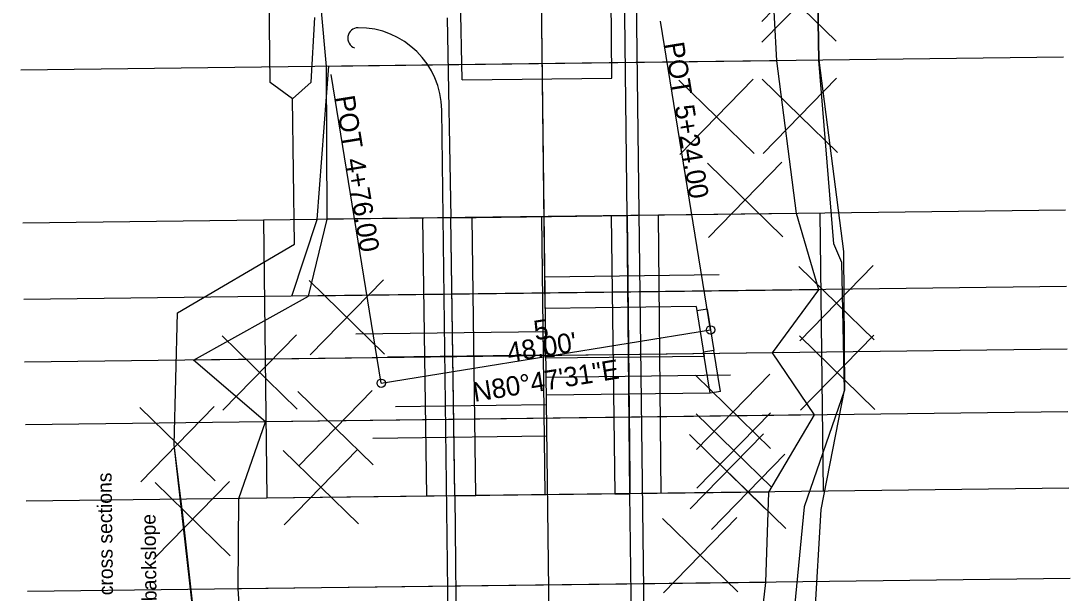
# Model space of a CAD drawing. Extents: x 2341000 to 2341204, y 624110 to 624511.
# Drawn here: x 2341050.8 to 2341201.7, y 624284.3 to 624366.6 of the extents above; entities that cross this region are included whole.
import ezdxf

# ---------------------------------------------------------------- set-up
doc = ezdxf.new("R2010")
doc.units = 0
for name, color, linetype in [('GE_P_Alignment', 7, 'Continuous'), ('GE_P_Alignment_1000_Bearings', 7, 'Continuous'), ('GE_P_Alignment_1000_Cardinal_Points', 7, 'Continuous'), ('GE_P_Alignment_1000_Distances', 7, 'Continuous'), ('GE_P_Alignment_1000_Stations', 7, 'Continuous'), ('GE_P_Alignment_100_Bearings', 7, 'Continuous'), ('GE_P_Alignment_100_Cardinal_Points', 7, 'Continuous'), ('GE_P_Alignment_100_Distances', 7, 'Continuous'), ('GE_P_Alignment_100_Stations', 7, 'Continuous'), ('GE_P_Alignment_500_Bearings', 7, 'Continuous'), ('GE_P_Alignment_500_Cardinal_Points', 7, 'Continuous'), ('GE_P_Alignment_500_Distances', 7, 'Continuous'), ('GE_P_Alignment_500_Stations', 7, 'Continuous'), ('PV_P_EOP', 7, 'Continuous'), ('PV_P_Joint', 7, 'Continuous'), ('PV_P_Shoulder', 7, 'Continuous'), ('RD_P_GR_Lt', 7, 'Continuous'), ('RD_P_GR_Rt', 7, 'Continuous'), ('RW_P_Const_Limits', 7, 'Continuous'), ('SC_Scratch1', 7, 'Continuous'), ('SC_Scratch10', 7, 'Continuous'), ('SC_Scratch2', 7, 'Continuous'), ('SC_Scratch3', 7, 'Continuous'), ('SC_Scratch5', 7, 'Continuous'), ('VG_P_Cells', 7, 'Continuous')]:
    doc.layers.add(name, color=color, linetype=linetype)

msp = doc.modelspace()

# ---------------------------------------------------------------- linework, layer by layer
at = {"layer": 'GE_P_Alignment'}
msp.add_line((2341102.63, 624314.5), (2341150.02, 624322.18), dxfattribs=at)
at = {"layer": 'GE_P_Alignment_1000_Cardinal_Points'}
for p, q in [((2341150.02, 624322.18), (2341142.81, 624366.6)), ((2341102.63, 624314.5), (2341095.43, 624358.92))]:
    msp.add_line(p, q, dxfattribs=at)
for centre in [(2341150.02, 624322.18), (2341102.63, 624314.5)]:
    msp.add_circle(centre, 0.6, dxfattribs=at)
at = {"layer": 'GE_P_Alignment_1000_Stations'}
msp.add_line((2341126.32, 624318.34), (2341126.13, 624319.53), dxfattribs=at)
at = {"layer": 'GE_P_Alignment_100_Cardinal_Points'}
for p, q in [((2341150.02, 624322.18), (2341142.81, 624366.6)), ((2341102.63, 624314.5), (2341095.43, 624358.92))]:
    msp.add_line(p, q, dxfattribs=at)
for centre in [(2341150.02, 624322.18), (2341102.63, 624314.5)]:
    msp.add_circle(centre, 0.6, dxfattribs=at)
at = {"layer": 'GE_P_Alignment_100_Stations'}
msp.add_line((2341126.32, 624318.34), (2341126, 624320.32), dxfattribs=at)
at = {"layer": 'GE_P_Alignment_500_Cardinal_Points'}
for p, q in [((2341150.02, 624322.18), (2341142.81, 624366.6)), ((2341102.63, 624314.5), (2341095.43, 624358.92))]:
    msp.add_line(p, q, dxfattribs=at)
for centre in [(2341150.02, 624322.18), (2341102.63, 624314.5)]:
    msp.add_circle(centre, 0.6, dxfattribs=at)
at = {"layer": 'GE_P_Alignment_500_Stations'}
msp.add_line((2341126.32, 624318.34), (2341126, 624320.32), dxfattribs=at)
at = {"layer": 'PV_P_EOP'}
for p, q in [((2341135.73, 624338.59), (2341115.74, 624338.34)), ((2341116.23, 624298.34), (2341115.74, 624338.34)), ((2341135.73, 624338.59), (2341136.23, 624298.59)), ((2341136.23, 624298.59), (2341116.23, 624298.34))]:
    msp.add_line(p, q, dxfattribs=at)
at = {"layer": 'PV_P_Joint'}
msp.add_line((2341126.23, 624298.47), (2341125.73, 624338.46), dxfattribs=at)
at = {"layer": 'PV_P_Shoulder'}
for p, q in [((2341112.63, 624338.3), (2341115.74, 624338.34)), ((2341113.22, 624298.31), (2341112.63, 624338.3)), ((2341135.73, 624338.59), (2341138.01, 624338.62)), ((2341138.41, 624298.62), (2341138.01, 624338.62)), ((2341136.23, 624298.59), (2341138.41, 624298.62)), ((2341113.22, 624298.31), (2341116.23, 624298.34))]:
    msp.add_line(p, q, dxfattribs=at)
at = {"layer": 'RD_P_GR_Lt'}
msp.add_line((2341112.73, 624241.3), (2341111.35, 624353.79), dxfattribs=at)
for centre, radius, start, end in [((2341099.32, 624364.14), 1.5, 90.7079, 249.491), ((2341099.35, 624353.64), 12, 0.6999, 90.2246)]:
    msp.add_arc(centre, radius, start, end, dxfattribs=at)
at = {"layer": 'RD_P_GR_Rt'}
msp.add_line((2341140.75, 624255.64), (2341138.46, 624443.13), dxfattribs=at)
at = {"layer": 'RW_P_Const_Limits'}
for p, q in [((2341135.83, 624358.38), (2341134.66, 624485.59)), ((2341114.29, 624358.12), (2341112.45, 624452.18)), ((2341086.67, 624357.74), (2341086.19, 624396.46)), ((2341167.77, 624334.57), (2341165.58, 624360.98)), ((2341089.87, 624355.39), (2341086.67, 624357.74)), ((2341114.29, 624358.12), (2341135.83, 624358.38)), ((2341090.18, 624334.51), (2341089.87, 624355.39)), ((2341073.33, 624324.63), (2341090.18, 624334.51)), ((2341072.85, 624305.65), (2341073.33, 624324.63)), ((2341165.92, 624296.35), (2341169.27, 624313.52)), ((2341074.08, 624295.58), (2341072.85, 624305.65)), ((2341080.8, 624235.4), (2341074.08, 624295.58)), ((2341163.92, 624261.73), (2341165.92, 624296.35))]:
    msp.add_line(p, q, dxfattribs=at)
for points in [[(2341165.58, 624360.98), (2341164.88, 624402.48), (2341162.81, 624405.53), (2341162.54, 624410.92)], [(2341169.27, 624313.52), (2341168.91, 624331.89), (2341167.77, 624334.57)]]:
    msp.add_lwpolyline(points, dxfattribs=at)
at = {"layer": 'SC_Scratch1'}
for p, q in [((2341200.8, 624361.39), (2341050.81, 624359.54)), ((2341201.07, 624339.39), (2341051.08, 624337.54)), ((2341201.21, 624328.4), (2341051.22, 624326.54)), ((2341201.32, 624319.4), (2341051.33, 624317.54)), ((2341201.43, 624310.4), (2341051.44, 624308.54)), ((2341201.56, 624299.4), (2341051.58, 624297.54)), ((2341201.73, 624286.4), (2341051.74, 624284.55))]:
    msp.add_line(p, q, dxfattribs=at)
at = {"layer": 'SC_Scratch10'}
for points in [[(2341164.88, 624402.48), (2341165.58, 624360.98), (2341169.13, 624333.44), (2341169.27, 624313.52), (2341163.5, 624296.74), (2341160.04, 624261.02)], [(2341112.12, 624367.05), (2341112.63, 624338.3), (2341138.01, 624338.62), (2341137.31, 624400.34)], [(2341080.8, 624235.4), (2341072.85, 624305.65), (2341073.33, 624324.63), (2341090.18, 624334.51), (2341089.87, 624355.39), (2341092.56, 624357.81), (2341093.07, 624367.11)], [(2341139.03, 624251.23), (2341138.41, 624298.62), (2341113.22, 624298.31), (2341113.72, 624249.79)]]:
    msp.add_lwpolyline(points, dxfattribs=at)
at = {"layer": 'SC_Scratch2'}
for p, q in [((2341128.28, 624160.48), (2341124.26, 624485.46)), ((2341159.54, 624360.88), (2341094.77, 624360.08)), ((2341162.38, 624338.92), (2341094.86, 624338.08)), ((2341165.58, 624327.96), (2341092.17, 624327.05)), ((2341158.94, 624318.87), (2341075.63, 624317.84)), ((2341164.96, 624309.95), (2341086.01, 624308.97)), ((2341158.38, 624298.86), (2341082.17, 624297.92)), ((2341157.95, 624285.86), (2341082.07, 624284.92))]:
    msp.add_line(p, q, dxfattribs=at)
for points in [[(2341155.11, 624260.82), (2341157.95, 624285.86), (2341158.38, 624298.86), (2341164.96, 624309.95), (2341158.94, 624318.87), (2341165.58, 624327.96), (2341162.38, 624338.92), (2341159.54, 624360.88), (2341158.21, 624385.87), (2341157.54, 624410.86), (2341158.38, 624435.87), (2341158.1, 624458.4)], [(2341155.11, 624260.82), (2341157.95, 624285.86), (2341158.38, 624298.86), (2341164.96, 624309.95), (2341158.94, 624318.87), (2341165.58, 624327.96), (2341162.38, 624338.92), (2341159.54, 624360.88), (2341158.21, 624385.87), (2341157.54, 624410.86), (2341158.38, 624435.87)], [(2341100.88, 624160.14), (2341094.03, 624185.06), (2341090.66, 624210.02), (2341083.8, 624234.94), (2341083.68, 624259.94), (2341082.07, 624284.92), (2341082.17, 624297.92), (2341086.01, 624308.97), (2341075.63, 624317.84), (2341092.17, 624327.05), (2341094.86, 624338.08), (2341094.77, 624360.08), (2341092.5, 624385.06), (2341096.91, 624410.11), (2341097.8, 624435.13)], [(2341089.77, 624327.02), (2341093.4, 624338.06), (2341095.11, 624360.09)], [(2341083.8, 624234.94), (2341083.68, 624259.94), (2341082.07, 624284.92), (2341082.17, 624297.92)]]:
    msp.add_lwpolyline(points, dxfattribs=at)
at = {"layer": 'SC_Scratch3'}
for p, q in [((2341126.24, 624325.25), (2341125.73, 624366.12)), ((2341086.23, 624297.97), (2341085.74, 624337.97)), ((2341109.22, 624298.25), (2341108.63, 624338.24)), ((2341142.91, 624298.66), (2341142.51, 624338.66)), ((2341165.73, 624338.96), (2341166.23, 624298.96)), ((2341151.24, 624330.08), (2341126.18, 624329.77)), ((2341147.96, 624325.52), (2341126.24, 624325.25)), ((2341147.96, 624325.52), (2341149.11, 624318.37)), ((2341149.54, 624325.14), (2341148.05, 624324.9)), ((2341149.54, 624325.14), (2341150.5, 624319.22)), ((2341098.98, 624321.6), (2341126.28, 624321.94)), ((2341102.63, 624314.5), (2341150.02, 624322.18)), ((2341103.54, 624318.32), (2341126.32, 624318.6)), ((2341127.57, 624318.35), (2341126.28, 624318.33)), ((2341149.11, 624318.37), (2341126.33, 624318.09)), ((2341150.5, 624319.22), (2341149.02, 624318.98)), ((2341149.98, 624313.06), (2341149.02, 624318.98)), ((2341151.46, 624313.3), (2341150.5, 624319.22)), ((2341152.86, 624315.66), (2341126.36, 624315.34)), ((2341149.98, 624313.06), (2341126.39, 624312.77)), ((2341151.46, 624313.3), (2341149.98, 624313.06)), ((2341104.69, 624311.17), (2341126.41, 624311.43)), ((2341101.41, 624306.61), (2341126.47, 624306.92))]:
    msp.add_line(p, q, dxfattribs=at)
at = {"layer": 'SC_Scratch5'}
msp.add_lwpolyline([(2341113.21, 624298.31), (2341113.18, 624301.95), (2341112.63, 624338.3), (2341138.01, 624338.62), (2341138.38, 624300.97), (2341138.41, 624298.62)], close=True, dxfattribs=at)
at = {"layer": 'VG_P_Cells'}
for p, q in [((2341157.37, 624366.55), (2341167.93, 624377.37)), ((2341157.27, 624374.24), (2341168.1, 624363.68)), ((2341157.41, 624363.55), (2341167.96, 624374.37)), ((2341145.46, 624358.09), (2341156.29, 624347.53)), ((2341145.6, 624347.4), (2341156.15, 624358.23)), ((2341157.46, 624358.24), (2341168.29, 624347.68)), ((2341157.6, 624347.55), (2341168.15, 624358.37)), ((2341150.87, 624352.81), (2341150.87, 624352.81)), ((2341162.87, 624352.96), (2341162.87, 624352.96)), ((2341149.58, 624346.14), (2341160.41, 624335.58)), ((2341149.71, 624335.45), (2341160.27, 624346.28)), ((2341154.99, 624340.86), (2341154.99, 624340.86)), ((2341162.73, 624331.3), (2341173.55, 624320.75)), ((2341162.86, 624320.61), (2341173.42, 624331.44)), ((2341092.29, 624329.27), (2341103.11, 624318.71)), ((2341092.42, 624318.58), (2341102.98, 624329.4)), ((2341168.14, 624326.02), (2341168.14, 624326.02)), ((2341097.7, 624323.99), (2341097.7, 624323.99)), ((2341079.74, 624321.33), (2341090.56, 624310.77)), ((2341079.87, 624310.64), (2341090.43, 624321.46)), ((2341162.82, 624321.3), (2341173.65, 624310.75)), ((2341162.96, 624310.61), (2341173.52, 624321.44)), ((2341085.15, 624316.05), (2341085.15, 624316.05)), ((2341147.84, 624315.67), (2341158.66, 624305.11)), ((2341147.97, 624304.98), (2341158.53, 624315.8)), ((2341168.24, 624316.02), (2341168.24, 624316.02)), ((2341090.65, 624313.33), (2341101.47, 624302.77)), ((2341090.78, 624302.64), (2341101.34, 624313.46)), ((2341067.93, 624311.03), (2341078.75, 624300.47)), ((2341068.06, 624300.34), (2341078.62, 624311.16)), ((2341147.93, 624310.12), (2341158.76, 624299.56)), ((2341148.06, 624299.43), (2341158.62, 624310.25)), ((2341153.25, 624310.39), (2341153.25, 624310.39)), ((2341096.06, 624308.05), (2341096.06, 624308.05)), ((2341146.96, 624307.11), (2341157.78, 624296.55)), ((2341147.09, 624296.42), (2341157.65, 624307.24)), ((2341073.34, 624305.75), (2341073.34, 624305.75)), ((2341088.54, 624304.83), (2341099.36, 624294.27)), ((2341088.67, 624294.14), (2341099.23, 624304.96)), ((2341153.34, 624304.84), (2341153.34, 624304.84)), ((2341150, 624304.15), (2341160.82, 624293.59)), ((2341150.13, 624293.45), (2341160.69, 624304.28)), ((2341152.37, 624301.83), (2341152.37, 624301.83)), ((2341070.1, 624300.25), (2341080.92, 624289.69)), ((2341070.23, 624289.56), (2341080.79, 624300.38)), ((2341093.95, 624299.55), (2341093.95, 624299.55)), ((2341155.41, 624298.86), (2341155.41, 624298.86)), ((2341075.51, 624294.97), (2341075.51, 624294.97)), ((2341143.12, 624295.06), (2341153.94, 624284.5)), ((2341143.25, 624284.37), (2341153.81, 624295.19)), ((2341148.53, 624289.78), (2341148.53, 624289.78))]:
    msp.add_line(p, q, dxfattribs=at)

# ---------------------------------------------------------------- texts
at = {"layer": 'GE_P_Alignment_1000_Bearings'}
msp.add_text('N80°47\'31"E', height=2.8, rotation=9.2079, dxfattribs=at).set_placement((2341116.06, 624311.81))
at = {"layer": 'GE_P_Alignment_1000_Cardinal_Points'}
for s, p in [('POT', (2341143.39, 624363.36)), ('POT', (2341096.01, 624355.68)), ('5+24.00', (2341144.85, 624354.34)), ('4+76.00', (2341097.47, 624346.66))]:
    msp.add_text(s, height=2.8, rotation=279.2079, dxfattribs=at).set_placement(p)
at = {"layer": 'GE_P_Alignment_1000_Distances'}
msp.add_text("48.00'", height=2.8, rotation=9.2079, dxfattribs=at).set_placement((2341120.99, 624317.52))
at = {"layer": 'GE_P_Alignment_100_Bearings'}
msp.add_text('N80°47\'31"E', height=2.8, rotation=9.2079, dxfattribs=at).set_placement((2341116.06, 624311.81))
at = {"layer": 'GE_P_Alignment_100_Cardinal_Points'}
for s, p in [('POT', (2341143.39, 624363.36)), ('POT', (2341096.01, 624355.68)), ('5+24.00', (2341144.85, 624354.34)), ('4+76.00', (2341097.47, 624346.66))]:
    msp.add_text(s, height=2.8, rotation=279.2079, dxfattribs=at).set_placement(p)
at = {"layer": 'GE_P_Alignment_100_Distances'}
msp.add_text("48.00'", height=2.8, rotation=9.2079, dxfattribs=at).set_placement((2341120.99, 624317.52))
at = {"layer": 'GE_P_Alignment_100_Stations'}
msp.add_text('5', height=2.8, rotation=9.2079, dxfattribs=at).set_placement((2341124.81, 624320.68))
at = {"layer": 'GE_P_Alignment_500_Bearings'}
msp.add_text('N80°47\'31"E', height=2.8, rotation=9.2079, dxfattribs=at).set_placement((2341116.06, 624311.81))
at = {"layer": 'GE_P_Alignment_500_Cardinal_Points'}
for s, p in [('POT', (2341143.39, 624363.36)), ('POT', (2341096.01, 624355.68)), ('5+24.00', (2341144.85, 624354.34)), ('4+76.00', (2341097.47, 624346.66))]:
    msp.add_text(s, height=2.8, rotation=279.2079, dxfattribs=at).set_placement(p)
at = {"layer": 'GE_P_Alignment_500_Distances'}
msp.add_text("48.00'", height=2.8, rotation=9.2079, dxfattribs=at).set_placement((2341120.99, 624317.52))
at = {"layer": 'GE_P_Alignment_500_Stations'}
msp.add_text('5', height=2.8, rotation=9.2079, dxfattribs=at).set_placement((2341124.81, 624320.68))
at = {"layer": 'SC_Scratch2'}
for s, p in [('SC Scratch2 Color 29 (brown) = tie-down point on cross sections', (2341064.83, 624221.7)), ('SC Scratch2 Color 30 (gold, heavy) = top of ditch/backslope', (2341071.08, 624221.78))]:
    msp.add_text(s, height=2.0833, rotation=90.7079, dxfattribs=at).set_placement(p)

doc.saveas('drawing.dxf')
